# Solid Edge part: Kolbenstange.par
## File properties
Username: ahadarics
Dokumentum tartalom típus: 0
Author: ahadarics
Last saved by: ahadarics
Revision: 83
Sűrűség: 0,000 kg/m^3
Pontosság: 0,990
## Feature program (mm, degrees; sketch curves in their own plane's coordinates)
base feature "unnamed BaseFeature 1"
thread "unnamed Thread 1"
chamfer "Letörés_1" setback 0.7
sketch for "Kihúzás_1" plane through (54.25, 0, 0) normal (1, 0, 0) x-axis (0, -1, 0)
  circle centre (0, 0) radius 10
extrude "Kihúzás_1" add finite 26.5 along -normal
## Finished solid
Body 1: solid body, 13 faces, 23 edges, 12 vertices.
  Faces by surface: plane 9, cylinder 3, cone 1
  Edges by curve: line 12, circle 11
Bounding box of the edges (mm): 288.000 x 20.000 x 20.000, from (-233.75, -10, -10) to (54.25, 10, 10).
Cylindrical faces by radius (mm): R4 x2, R10 x1
Conical faces (half-angle, radius in mm at the cone's reference point): 45 deg R3.3 x1
Planar faces by outward normal: +x 3, +z 1, -x 4, -z 1
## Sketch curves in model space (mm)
circle centre (54.25, 0, 0) radius 10
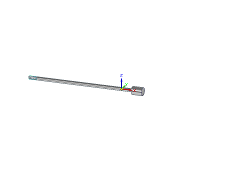
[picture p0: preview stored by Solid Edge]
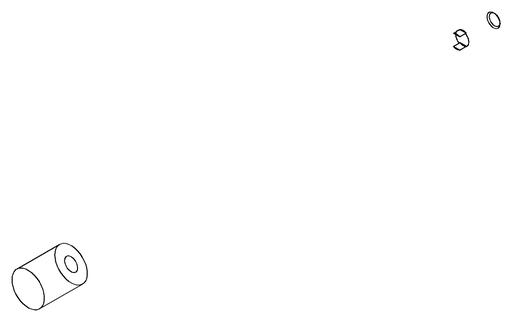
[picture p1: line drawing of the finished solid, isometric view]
